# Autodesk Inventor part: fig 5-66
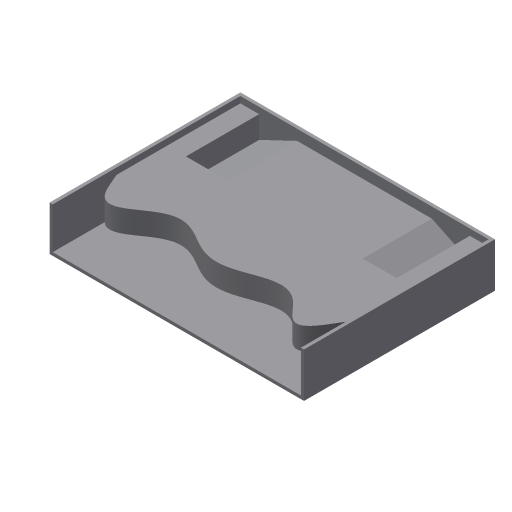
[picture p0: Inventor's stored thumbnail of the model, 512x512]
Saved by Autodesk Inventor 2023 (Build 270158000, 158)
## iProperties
Created: 2004-05
Part Number: fig 5-66
Document SubType Name: Modeling
Designer: CADCIM Technologies
Manufacturer: Standard
Standards Organization: Custom
Density: 1 g/cm^3
Material: Generic
Appearance: Default
Author: CADCIM Technologies
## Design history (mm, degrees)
sketch "Sketch1"
  geometry: L1 (-40, -30)-(40, -30); L2 (40, -30)-(40, 30); L3 (40, 30)-(-40, 30); L4 (-40, 30)-(-40, -30); 1 further point
  constraints: 8 end point, 2 parallel, 1 horizontal, 1 perpendicular, 1 other
  dimensions: "d0" = 80 distance of L1.start L1.end; "d1" = 60 distance of L3.end L1.start; "d2" = 30 distance from line of point (0, 0) L1; "d3" = 40 distance from line of point (0, 0) L4
extrude "Extrusion1" new body sketch "Sketch1" distance "d4" = 14; taper "d5" = 0 deg
shell "Shell1" dims "d6" = 1
workplane "Work Plane1"
sketch "Sketch2"
  geometry: L1 (78, -13)-(78, -11.813); L2 (0, -11.813)-(0, -13); L3 (0, -13)-(78, -13); L4 (0, -11.813)-(17.826, -3.295); L5 (17.826, -3.295)-(60.174, -3.295); L6 (60.174, -3.295)-(78, -11.813); L7 (79, -13.795)-(78, -13.795); L8 (78, 0)-(78, -13) reference; L9 (0, -13)-(0, 0) reference; L10 (78, -13)-(0, -13) reference
  constraints: 14 end point, 3 collinear, 2 equal length, 2 vertical, 1 horizontal alignment, 1 parallel, 1 point on line
extrude "Extrusion2" join sketch "Sketch2" stored distance "d8" = 14; taper "d9" = 0 deg
workplane "Work Plane2"
sketch "Sketch3"
  geometry: 7 further points
  constraints: 7 other
extrude "Extrusion7" join sketch "Sketch3" distance "d27" = 7; taper "d28" = 0 deg
body "Solid1"
other parameters: "d7" = 23, "d18" = 4, "d29" = 7
